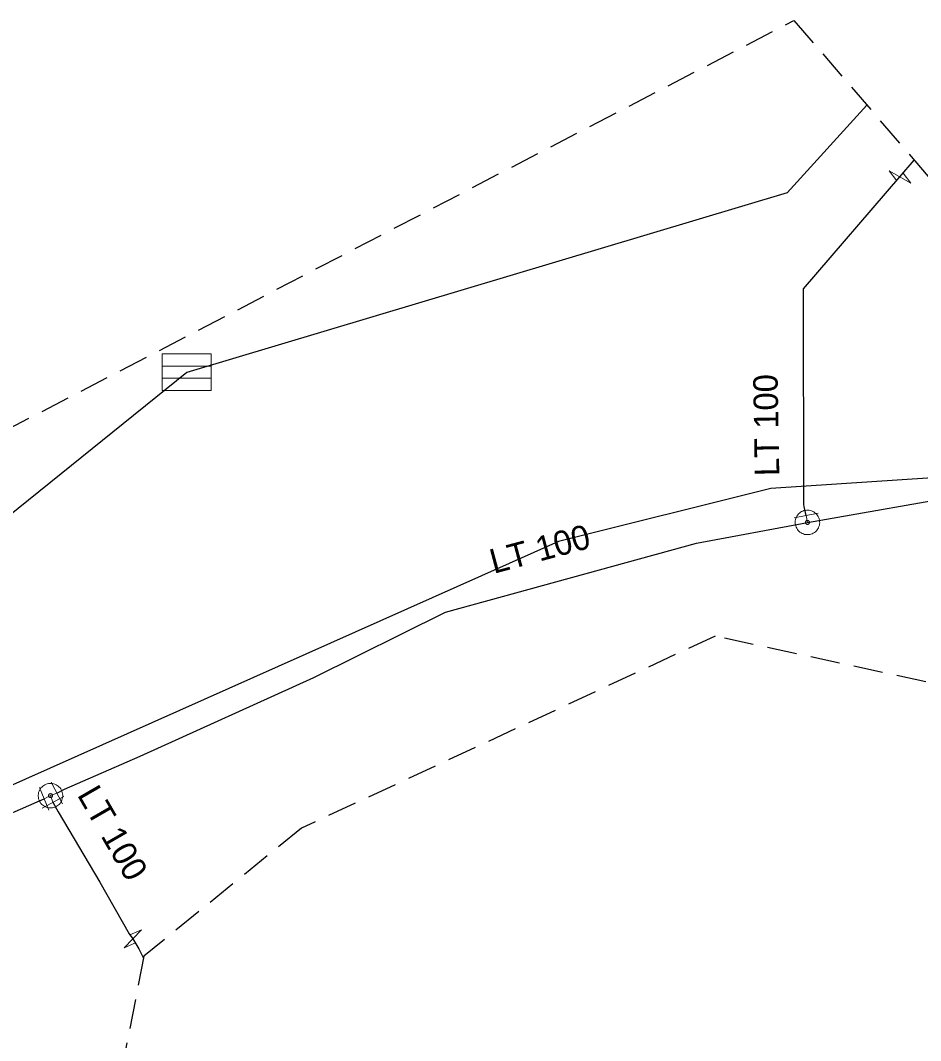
# Model space of a CAD drawing. Extents: x -688693 to -688474, y -974081 to -973994.
# Drawn here: x -688584.02 to -688547.29, y -974035.86 to -973994.23 of the extents above; entities that cross this region are included whole.
import ezdxf

# ---------------------------------------------------------------- set-up
doc = ezdxf.new("R2010")
doc.units = 0
doc.header["$LTSCALE"] = 0.4
doc.linetypes.add('MEDIUM_DASHED', pattern=[4.5, 3, -1.5])
for name, color, linetype, lineweight in [('1', 7, 'MEDIUM_DASHED', 25), ('14', 7, 'Continuous', 25), ('17', 7, 'Continuous', 25), ('22', 7, 'Continuous', 13), ('34', 7, 'Continuous', 13), ('47', 7, 'Continuous', 13)]:
    doc.layers.add(name, color=color, linetype=linetype, lineweight=lineweight)

msp = doc.modelspace()

# ---------------------------------------------------------------- linework, layer by layer
at = {"layer": '1'}
msp.add_lwpolyline([(-688692.931, -974052.713), (-688674.241, -974042.463), (-688662.987, -974051.708), (-688552.455, -973994.231), (-688543.813, -974004.28), (-688496.988, -974010.309), (-688488.949, -974009.103), (-688474.077, -974014.529), (-688476.69, -974033.621), (-688494.978, -974032.616), (-688541.804, -974022.367), (-688555.67, -974019.352), (-688572.552, -974027.19), (-688578.982, -974032.415), (-688581.193, -974043.669), (-688636.057, -974069.393), (-688655.149, -974067.182), (-688651.532, -974076.829), (-688666.202, -974081.049), (-688669.82, -974071.805), (-688685.294, -974080.647), (-688689.113, -974064.369), (-688682.883, -974060.751)], close=True, dxfattribs=at)
at = {"layer": '14'}
msp.add_line((-688577.23, -974008.592), (-688598.575, -974025.813), dxfattribs=at)
at = {"layer": '14', "lineweight": 13}
for p, q in [((-688551.906, -974014.715), (-688551.963, -974014.432)), ((-688582.793, -974025.864), (-688582.692, -974026.133))]:
    msp.add_line(p, q, dxfattribs=at)
at = {"layer": '14'}
for points in [[(-688549.483, -973997.686), (-688552.727, -974001.266), (-688577.23, -974008.592)], [(-688544.118, -974012.713), (-688553.402, -974013.335), (-688562.069, -974015.498), (-688588.977, -974027.483)]]:
    msp.add_lwpolyline(points, dxfattribs=at)
at = {"layer": '14', "lineweight": 13}
msp.add_lwpolyline([(-688583.05, -974025.995), (-688582.793, -974025.864), (-688582.535, -974025.761)], dxfattribs=at)
at = {"layer": '17'}
msp.add_line((-688548.133, -974000.62), (-688547.548, -973999.936), dxfattribs=at)
for points in [[(-688551.963, -974014.432), (-688552.037, -974014.063), (-688552.054, -974013.978), (-688552.067, -974005.18), (-688548.133, -974000.62)], [(-688551.906, -974014.715), (-688545.087, -974013.515), (-688537.316, -974014.752), (-688531.5, -974015.651), (-688521.409, -974017.455), (-688501.548, -974020.969), (-688495.708, -974022.214), (-688494.963, -974022.656), (-688494.688, -974022.862)], [(-688582.535, -974025.761), (-688582.227, -974025.598), (-688579.138, -974024.252), (-688572.05, -974021.044), (-688566.67, -974018.377), (-688556.436, -974015.561), (-688551.906, -974014.715)], [(-688602.322, -974035.098), (-688601.921, -974034.916), (-688600.46, -974034.151), (-688585.27, -974026.962), (-688583.34, -974026.112), (-688583.05, -974025.995)], [(-688582.692, -974026.133), (-688582.48, -974026.517), (-688580.785, -974029.392), (-688579.579, -974031.5), (-688579.436, -974031.702)], [(-688579.436, -974031.702), (-688579.188, -974032.113), (-688578.998, -974032.496)]]:
    msp.add_lwpolyline(points, dxfattribs=at)
at = {"layer": '22'}
for p, q in [((-688578.241, -974008.335), (-688576.241, -974008.335)), ((-688578.241, -974008.835), (-688576.241, -974008.835))]:
    msp.add_line(p, q, dxfattribs=at)
msp.add_lwpolyline([(-688578.241, -974007.835), (-688576.241, -974007.835), (-688576.241, -974009.335), (-688578.241, -974009.335)], close=True, dxfattribs=at)
at = {"layer": '34'}
for p, q in [((-688552.453, -974014.53), (-688551.472, -974014.334)), ((-688583.237, -974025.531), (-688582.863, -974026.458)), ((-688582.769, -974025.319), (-688582.301, -974026.202)), ((-688582.253, -974025.892), (-688583.13, -974026.372))]:
    msp.add_line(p, q, dxfattribs=at)
at = {"layer": '47'}
for p, q in [((-688548.575, -974000.367), (-688548.264, -974000.772)), ((-688579.083, -974031.334), (-688579.551, -974031.537))]:
    msp.add_line(p, q, dxfattribs=at)
for points in [[(-688548.575, -974000.367), (-688547.69, -974000.872), (-688548.001, -974000.467)], [(-688579.083, -974031.334), (-688579.788, -974032.069), (-688579.32, -974031.866)]]:
    msp.add_lwpolyline(points, dxfattribs=at)
for points in [[(-688551.414, -974014.623), (-688551.426, -974014.572), (-688551.444, -974014.523), (-688551.467, -974014.476), (-688551.494, -974014.431), (-688551.526, -974014.389), (-688551.562, -974014.351), (-688551.602, -974014.318), (-688551.645, -974014.289), (-688551.691, -974014.263), (-688551.739, -974014.243), (-688551.79, -974014.228), (-688551.841, -974014.219), (-688551.893, -974014.215), (-688551.946, -974014.216), (-688551.997, -974014.223), (-688552.048, -974014.235), (-688552.097, -974014.253), (-688552.145, -974014.276), (-688552.189, -974014.303), (-688552.231, -974014.335), (-688552.269, -974014.371), (-688552.303, -974014.411), (-688552.332, -974014.454), (-688552.358, -974014.5), (-688552.377, -974014.548), (-688552.392, -974014.599), (-688552.402, -974014.65), (-688552.405, -974014.702), (-688552.404, -974014.755), (-688552.397, -974014.806), (-688552.385, -974014.857), (-688552.367, -974014.906), (-688552.345, -974014.954), (-688552.317, -974014.998), (-688552.285, -974015.04), (-688552.25, -974015.078), (-688552.21, -974015.112), (-688552.167, -974015.142), (-688552.12, -974015.167), (-688552.072, -974015.186), (-688552.021, -974015.201), (-688551.971, -974015.211), (-688551.918, -974015.214), (-688551.865, -974015.213), (-688551.814, -974015.206), (-688551.763, -974015.194), (-688551.714, -974015.176), (-688551.667, -974015.154), (-688551.622, -974015.126), (-688551.58, -974015.094), (-688551.542, -974015.059), (-688551.509, -974015.019), (-688551.479, -974014.976), (-688551.454, -974014.929), (-688551.434, -974014.881), (-688551.419, -974014.83), (-688551.41, -974014.78), (-688551.406, -974014.727), (-688551.407, -974014.674)], [(-688551.825, -974014.699), (-688551.827, -974014.691), (-688551.83, -974014.683), (-688551.833, -974014.676), (-688551.838, -974014.668), (-688551.843, -974014.661), (-688551.849, -974014.655), (-688551.856, -974014.649), (-688551.863, -974014.644), (-688551.87, -974014.641), (-688551.878, -974014.637), (-688551.887, -974014.635), (-688551.895, -974014.633), (-688551.903, -974014.633), (-688551.912, -974014.632), (-688551.921, -974014.634), (-688551.929, -974014.636), (-688551.937, -974014.639), (-688551.944, -974014.642), (-688551.952, -974014.647), (-688551.959, -974014.652), (-688551.965, -974014.658), (-688551.971, -974014.665), (-688551.976, -974014.672), (-688551.98, -974014.68), (-688551.983, -974014.687), (-688551.985, -974014.696), (-688551.987, -974014.704), (-688551.987, -974014.712), (-688551.988, -974014.721), (-688551.986, -974014.73), (-688551.984, -974014.738), (-688551.981, -974014.746), (-688551.978, -974014.753), (-688551.973, -974014.761), (-688551.968, -974014.768), (-688551.963, -974014.774), (-688551.955, -974014.78), (-688551.948, -974014.785), (-688551.94, -974014.789), (-688551.933, -974014.792), (-688551.924, -974014.794), (-688551.916, -974014.796), (-688551.908, -974014.796), (-688551.899, -974014.797), (-688551.89, -974014.795), (-688551.882, -974014.793), (-688551.874, -974014.79), (-688551.867, -974014.787), (-688551.859, -974014.782), (-688551.852, -974014.777), (-688551.846, -974014.772), (-688551.84, -974014.764), (-688551.835, -974014.757), (-688551.832, -974014.75), (-688551.828, -974014.742), (-688551.826, -974014.733), (-688551.824, -974014.725), (-688551.824, -974014.717), (-688551.823, -974014.708)], [(-688582.347, -974025.636), (-688582.373, -974025.591), (-688582.404, -974025.549), (-688582.439, -974025.511), (-688582.478, -974025.475), (-688582.52, -974025.444), (-688582.566, -974025.418), (-688582.614, -974025.397), (-688582.663, -974025.381), (-688582.714, -974025.37), (-688582.766, -974025.364), (-688582.819, -974025.364), (-688582.871, -974025.37), (-688582.922, -974025.381), (-688582.972, -974025.397), (-688583.02, -974025.418), (-688583.065, -974025.444), (-688583.107, -974025.475), (-688583.146, -974025.511), (-688583.181, -974025.549), (-688583.212, -974025.591), (-688583.238, -974025.637), (-688583.259, -974025.685), (-688583.276, -974025.735), (-688583.287, -974025.785), (-688583.292, -974025.837), (-688583.292, -974025.89), (-688583.287, -974025.942), (-688583.275, -974025.993), (-688583.259, -974026.043), (-688583.238, -974026.091), (-688583.212, -974026.136), (-688583.181, -974026.178), (-688583.146, -974026.218), (-688583.107, -974026.252), (-688583.065, -974026.283), (-688583.02, -974026.309), (-688582.972, -974026.331), (-688582.922, -974026.347), (-688582.871, -974026.358), (-688582.819, -974026.363), (-688582.766, -974026.363), (-688582.714, -974026.358), (-688582.663, -974026.346), (-688582.613, -974026.33), (-688582.565, -974026.309), (-688582.52, -974026.283), (-688582.478, -974026.252), (-688582.439, -974026.218), (-688582.404, -974026.178), (-688582.373, -974026.136), (-688582.347, -974026.091), (-688582.326, -974026.043), (-688582.31, -974025.993), (-688582.299, -974025.942), (-688582.293, -974025.89), (-688582.293, -974025.837), (-688582.299, -974025.786), (-688582.31, -974025.734), (-688582.326, -974025.684)], [(-688582.719, -974025.826), (-688582.724, -974025.818), (-688582.729, -974025.812), (-688582.734, -974025.806), (-688582.741, -974025.8), (-688582.748, -974025.795), (-688582.755, -974025.791), (-688582.763, -974025.787), (-688582.771, -974025.784), (-688582.78, -974025.783), (-688582.788, -974025.782), (-688582.797, -974025.782), (-688582.806, -974025.783), (-688582.814, -974025.785), (-688582.822, -974025.786), (-688582.83, -974025.79), (-688582.838, -974025.795), (-688582.844, -974025.8), (-688582.85, -974025.805), (-688582.856, -974025.812), (-688582.861, -974025.819), (-688582.865, -974025.826), (-688582.869, -974025.834), (-688582.872, -974025.842), (-688582.874, -974025.851), (-688582.874, -974025.859), (-688582.874, -974025.868), (-688582.873, -974025.877), (-688582.871, -974025.885), (-688582.87, -974025.893), (-688582.866, -974025.901), (-688582.861, -974025.909), (-688582.856, -974025.915), (-688582.851, -974025.921), (-688582.844, -974025.927), (-688582.837, -974025.932), (-688582.83, -974025.937), (-688582.822, -974025.94), (-688582.814, -974025.943), (-688582.805, -974025.945), (-688582.797, -974025.945), (-688582.788, -974025.945), (-688582.779, -974025.944), (-688582.771, -974025.942), (-688582.763, -974025.941), (-688582.755, -974025.937), (-688582.747, -974025.932), (-688582.741, -974025.927), (-688582.735, -974025.922), (-688582.729, -974025.915), (-688582.724, -974025.908), (-688582.719, -974025.901), (-688582.716, -974025.893), (-688582.713, -974025.885), (-688582.712, -974025.876), (-688582.711, -974025.868), (-688582.711, -974025.859), (-688582.712, -974025.85), (-688582.714, -974025.842), (-688582.715, -974025.834)]]:
    msp.add_lwpolyline(points, close=True, dxfattribs=at)

# ---------------------------------------------------------------- texts
at = {"layer": '1'}
for rotation, p in [(91, (-688553.052, -974012.818)), (15, (-688564.706, -974016.814)), (300, (-688581.725, -974025.829))]:
    msp.add_text('LT 100', height=1, rotation=rotation, dxfattribs=at).set_placement(p)

doc.saveas('drawing.dxf')
